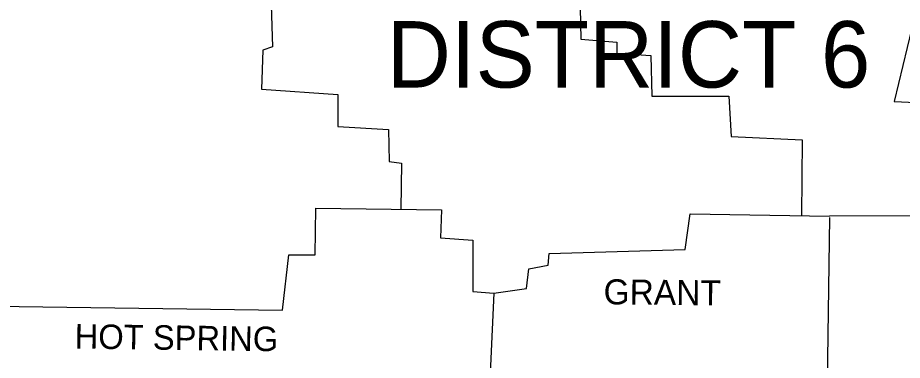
# Model space of a CAD drawing. Extents: x -13171 to 18763, y -8840 to 11152.
# Drawn here: x 12315 to 13801, y 7050 to 7625 of the extents above; entities that cross this region are included whole.
import ezdxf

# ---------------------------------------------------------------- set-up
doc = ezdxf.new("R2010")
doc.units = 0
for name, color, linetype in [('Level 1', 7, 'Continuous'), ('Level 2', 7, 'Continuous'), ('Level 3', 7, 'Continuous')]:
    doc.layers.add(name, color=color, linetype=linetype)

msp = doc.modelspace()

# ---------------------------------------------------------------- linework, layer by layer
at = {"layer": 'Level 1'}
for points in [[(13780.408528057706, 8074.393472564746), (13837.15612338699, 8070.47984524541), (13838.134530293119, 7696.7284411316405), (13787.257375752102, 7484.414161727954), (13895.860532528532, 7479.52212750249), (13894.844193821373, 7292.515822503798)], [(13018.229617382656, 7830.219821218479), (13134.660028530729, 7822.942920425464), (13130.74640124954, 7700.642068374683), (13258.917694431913, 7695.7500342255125), (13260.874508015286, 7589.103690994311), (13321.53573062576, 7584.211657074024), (13321.53573062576, 7565.621927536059), (13378.283326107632, 7561.708300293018), (13380.240139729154, 7493.219822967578), (13509.389839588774, 7493.219822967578), (13513.303466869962, 7425.709752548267), (13632.669098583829, 7419.83931172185), (13631.689211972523, 7292.454043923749)], [(12593.638354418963, 7710.504222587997), (12739.383674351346, 7699.663661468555), (12743.297301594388, 7576.384402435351), (12726.664385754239, 7570.5139616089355), (12724.707572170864, 7504.960704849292), (12852.878865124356, 7496.155043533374), (12852.878865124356, 7442.34266857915), (12938.000258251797, 7437.45063442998), (12938.978665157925, 7383.638259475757), (12959.525208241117, 7380.703038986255), (12958.480338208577, 7303.382645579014)], [(14798.930024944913, 7405.163209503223), (14429.092247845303, 7414.947277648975), (14427.135434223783, 7294.603239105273), (13678.654218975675, 7291.668018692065)], [(12196.43269704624, 7142.025605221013), (12759.930217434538, 7134.144520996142), (12770.692692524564, 7227.093168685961), (12814.720999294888, 7227.093168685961), (12815.699406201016, 7305.365714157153), (13027.035278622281, 7302.430493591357), (13025.078465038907, 7255.466966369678), (13079.869246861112, 7251.5533390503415), (13079.869246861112, 7165.45353916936), (13115.09189216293, 7162.518318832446)], [(13115.09189216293, 7162.518318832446), (13169.882673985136, 7170.345573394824), (13173.796301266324, 7203.611405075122), (13206.083726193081, 7209.481845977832), (13208.040539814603, 7229.049982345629), (13436.0093283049, 7235.898830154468), (13444.81498958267, 7295.581646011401), (13678.654218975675, 7291.668018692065)], [(13678.654218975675, 7289.711205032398), (13672.783778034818, 6894.434850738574), (13650.280421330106, 6893.456443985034), (13647.345200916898, 6647.876332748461)], [(13115.09189216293, 7162.518318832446), (13103.35101035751, 6906.175732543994), (13094.545349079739, 6909.11095310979), (13095.523755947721, 6776.047625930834)]]:
    msp.add_lwpolyline(points, dxfattribs=at)

# ---------------------------------------------------------------- texts
at = {"layer": 'Level 2'}
for s, height, rotation, p in [('GRANT', 42.07344995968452, 359.4031917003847, (13299.032373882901, 7143.928589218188)), ('HOT SPRING', 41.09308632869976, 359.22157224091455, (12410.638983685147, 7069.569671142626))]:
    msp.add_text(s, height=height, rotation=rotation, dxfattribs=at).set_placement(p)
at = {"layer": 'Level 3'}
msp.add_text('DISTRICT 6', height=111.53837717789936, dxfattribs=at).set_placement((12935.065037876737, 7507.895925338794))

doc.saveas('drawing.dxf')
